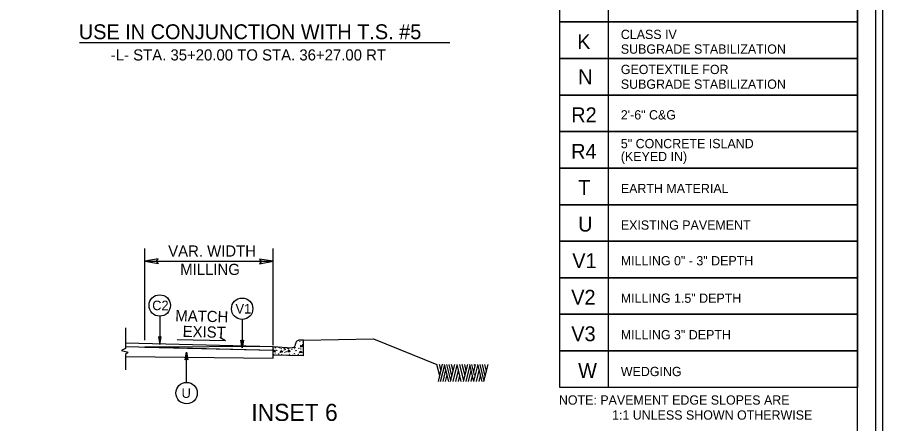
# Model space of a CAD drawing. Extents: x 573748 to 574632, y -54663 to -53209.
# Drawn here: x 574164.6 to 574281, y -53807.2 to -53752.5 of the extents above; entities that cross this region are included whole.
import ezdxf

# ---------------------------------------------------------------- set-up
doc = ezdxf.new("R2010")
doc.units = 0
for name, color, linetype in [('Prop Dimension', 7, 'Continuous'), ('Prop Dimension Text', 7, 'Continuous'), ('Prop Pavement Schedule Description CELL', 7, 'Continuous'), ('Prop Terminator CELL', 7, 'Continuous'), ('Sheet Plot Border Inside CELL', 7, 'Continuous'), ('Sheet Plot Border Outside CELL', 7, 'Continuous'), ('Sheet Typical CELL', 7, 'Continuous'), ('Typical Arrow Superelevation CELL', 7, 'Continuous'), ('Typical ID Circle CELL', 7, 'Continuous'), ('Typical Pavement Slope CELL', 7, 'Continuous'), ('Typical Terminator CELL', 7, 'Continuous'), ('Typical Text General CELL', 7, 'Continuous'), ('Typical Text ID Circle CELL', 7, 'Continuous')]:
    doc.layers.add(name, color=color, linetype=linetype)

msp = doc.modelspace()

# ---------------------------------------------------------------- linework, layer by layer
at = {"layer": 'Prop Dimension'}
for p, q in [((574181.74, -53795.97), (574181.74, -53783.61)), ((574198.97, -53796.66), (574198.97, -53783.61)), ((574181.74, -53785.35), (574198.97, -53785.35)), ((574179.11, -53794.3), (574179.11, -53797.07)), ((574203.07, -53795.99), (574202.52, -53795.98)), ((574203.07, -53795.99), (574212.48, -53795.79)), ((574203.07, -53798.09), (574203.07, -53795.99)), ((574212.48, -53795.79), (574221.01, -53799.23)), ((574179.11, -53797.07), (574178.61, -53797.37)), ((574178.61, -53797.37), (574179.47, -53797.57)), ((574179.47, -53797.57), (574179.11, -53797.92)), ((574198.97, -53796.81), (574181.74, -53796.91)), ((574181.74, -53796.91), (574198.97, -53797.32)), ((574198.97, -53797.99), (574198.97, -53796.81)), ((574198.97, -53796.81), (574201.47, -53796.98)), ((574198.97, -53797.32), (574198.97, -53796.81)), ((574199, -53797.52), (574199.19, -53797.27)), ((574199.26, -53797.51), (574199, -53797.52)), ((574199.19, -53797.27), (574199.26, -53797.51)), ((574199.94, -53797.62), (574200.08, -53797.38)), ((574200.29, -53797.54), (574199.94, -53797.62)), ((574200.08, -53797.38), (574200.29, -53797.54)), ((574200.96, -53797.53), (574201.14, -53797.29)), ((574201.21, -53797.53), (574200.96, -53797.53)), ((574201.14, -53797.29), (574201.21, -53797.53)), ((574202.01, -53796.49), (574202.01, -53796.47)), ((574202.55, -53797.68), (574202.69, -53797.45)), ((574202.9, -53797.61), (574202.55, -53797.68)), ((574202.65, -53796.68), (574202.68, -53796.87)), ((574202.97, -53796.79), (574202.65, -53796.68)), ((574202.68, -53796.87), (574202.97, -53796.79)), ((574202.69, -53797.45), (574202.9, -53797.61)), ((574179.11, -53797.92), (574179.11, -53799.97)), ((574179.11, -53798.19), (574198.97, -53798.39)), ((574198.97, -53798.39), (574198.97, -53797.99)), ((574203.07, -53798.09), (574198.97, -53797.99)), ((574221.39, -53800.78), (574221.01, -53799.23)), ((574221.21, -53801.52), (574221.77, -53799.22)), ((574221.57, -53800.1), (574221.35, -53799.23)), ((574221.51, -53801.52), (574222.06, -53799.3)), ((574222.61, -53801.52), (574222.05, -53799.23)), ((574222.61, -53800.3), (574222.35, -53799.23)), ((574223.03, -53800.76), (574222.65, -53799.23)), ((574222.85, -53801.52), (574223.41, -53799.23)), ((574223.2, -53800.11), (574222.98, -53799.23)), ((574223.21, -53801.52), (574223.75, -53799.34)), ((574224.29, -53801.52), (574223.72, -53799.23)), ((574224.62, -53801.45), (574224.08, -53799.23)), ((574224.8, -53800.74), (574224.43, -53799.23)), ((574224.61, -53801.52), (574225.17, -53799.23)), ((574224.96, -53800.08), (574224.75, -53799.23)), ((574224.95, -53801.52), (574225.48, -53799.35)), ((574225.99, -53801.55), (574225.42, -53799.26)), ((574226.07, -53800.7), (574225.72, -53799.26)), ((574225.98, -53800.23), (574226.22, -53799.26)), ((574225.99, -53801.55), (574226.53, -53799.38)), ((574226.07, -53799.37), (574226.05, -53799.26)), ((574226.11, -53799.34), (574226.09, -53799.23)), ((574227.08, -53801.55), (574226.51, -53799.26)), ((574227.35, -53801.48), (574226.81, -53799.26)), ((574227.52, -53800.82), (574227.13, -53799.26)), ((574227.34, -53801.55), (574227.9, -53799.26)), ((574227.69, -53800.14), (574227.48, -53799.26)), ((574221.85, -53801.52), (574222.23, -53799.96)), ((574222.17, -53801.52), (574222.39, -53800.62)), ((574222.88, -53801.38), (574222.61, -53800.3)), ((574223.56, -53801.52), (574223.92, -53800.03)), ((574223.9, -53801.52), (574224.09, -53800.73)), ((574225.25, -53801.55), (574225.62, -53800.07)), ((574225.61, -53801.55), (574225.79, -53800.78)), ((574226.01, -53800.11), (574225.98, -53800.02)), ((574226.35, -53801.55), (574226.71, -53800.07)), ((574226.7, -53801.55), (574226.88, -53800.78))]:
    msp.add_line(p, q, dxfattribs=at)
for centre in [(574202.58, -53796.14), (574203.04, -53796.23), (574199.02, -53797.05), (574199.26, -53797.02), (574199.3, -53796.92), (574199.46, -53797.33), (574199.83, -53796.99), (574200.08, -53797.1), (574200.45, -53797.32), (574200.49, -53797.11), (574200.56, -53797.62), (574200.61, -53797.19), (574200.76, -53797.53), (574200.84, -53797), (574201.04, -53797.12), (574201.45, -53797.05), (574201.5, -53797.26), (574201.81, -53797.45), (574201.88, -53797.09), (574201.92, -53796.99), (574202.07, -53797.39), (574202.45, -53797.06), (574202.7, -53797.17), (574202.92, -53796.6), (574199.01, -53797.88), (574199.25, -53797.7), (574199.37, -53797.95), (574199.74, -53797.83), (574200.1, -53797.92), (574200.42, -53797.96), (574200.86, -53798.02), (574201.2, -53797.89), (574201.63, -53797.95), (574201.87, -53797.77), (574201.98, -53798.01), (574202.36, -53797.89), (574202.72, -53797.99)]:
    msp.add_circle(centre, 0.0168, dxfattribs=at)
for centre, start, end in [((574202.51, -53796.48), 88.5196, 178.5196), ((574201.51, -53796.48), 266.1351, 358.5196)]:
    msp.add_arc(centre, 0.502, start, end, dxfattribs=at)
at = {"layer": 'Prop Pavement Schedule Description CELL'}
for points in [[(574244.08, -53753.13), (574237.56, -53753.13), (574237.56, -53748.22), (574277.57, -53748.22), (574277.57, -53753.13), (574244.08, -53753.13), (574244.08, -53748.22)], [(574244.08, -53758.05), (574237.56, -53758.05), (574237.56, -53753.13), (574277.57, -53753.13), (574277.57, -53758.05), (574244.08, -53758.05), (574244.08, -53753.13)], [(574244.08, -53762.97), (574237.56, -53762.97), (574237.56, -53758.05), (574277.57, -53758.05), (574277.57, -53762.97), (574244.08, -53762.97), (574244.08, -53758.05)], [(574244.08, -53767.89), (574237.56, -53767.89), (574237.56, -53762.97), (574277.57, -53762.97), (574277.57, -53767.89), (574244.08, -53767.89), (574244.08, -53762.97)], [(574244.08, -53772.81), (574237.56, -53772.81), (574237.56, -53767.89), (574277.57, -53767.89), (574277.57, -53772.81), (574244.08, -53772.81), (574244.08, -53767.89)], [(574244.08, -53777.73), (574237.56, -53777.73), (574237.56, -53772.81), (574277.57, -53772.81), (574277.57, -53777.73), (574244.08, -53777.73), (574244.08, -53772.81)], [(574244.08, -53782.64), (574237.56, -53782.64), (574237.56, -53777.73), (574277.57, -53777.73), (574277.57, -53782.64), (574244.08, -53782.64), (574244.08, -53777.73)], [(574244.08, -53787.56), (574237.56, -53787.56), (574237.56, -53782.64), (574277.57, -53782.64), (574277.57, -53787.56), (574244.08, -53787.56), (574244.08, -53782.64)], [(574244.08, -53792.48), (574237.56, -53792.48), (574237.56, -53787.56), (574277.57, -53787.56), (574277.57, -53792.48), (574244.08, -53792.48), (574244.08, -53787.56)], [(574244.08, -53797.4), (574237.56, -53797.4), (574237.56, -53792.48), (574277.57, -53792.48), (574277.57, -53797.4), (574244.08, -53797.4), (574244.08, -53792.48)], [(574244.08, -53802.32), (574237.56, -53802.32), (574237.56, -53797.4), (574277.57, -53797.4), (574277.57, -53802.32), (574244.08, -53802.32), (574244.08, -53797.4)]]:
    msp.add_lwpolyline(points, dxfattribs=at)
at = {"layer": 'Prop Terminator CELL'}
for points in [[(574183.53, -53785.02), (574181.74, -53785.35), (574183.55, -53785.65), (574183.32, -53785.33)], [(574197.17, -53785.69), (574198.97, -53785.35), (574197.16, -53785.06), (574197.39, -53785.37)]]:
    msp.add_lwpolyline(points, close=True, dxfattribs=at)
at = {"layer": 'Sheet Plot Border Inside CELL'}
msp.add_lwpolyline([(574280.07, -53683.17), (573946.77, -53683.17), (573946.77, -53894.19), (574280.07, -53894.19)], close=True, dxfattribs=at)
at = {"layer": 'Sheet Plot Border Outside CELL'}
msp.add_lwpolyline([(574280.97, -53678.68), (573944.17, -53678.68), (573944.17, -53898.68), (574280.97, -53898.68)], close=True, dxfattribs=at)
at = {"layer": 'Sheet Typical CELL'}
msp.add_lwpolyline([(574277.57, -53683.68), (573977.57, -53683.68), (573977.57, -53893.68), (574277.57, -53893.68)], close=True, dxfattribs=at)
at = {"layer": 'Typical Arrow Superelevation CELL'}
for q in [(574186.08, -53795.92), (574191.82, -53795.6)]:
    msp.add_line((574192.6, -53796.08), q, dxfattribs=at)
at = {"layer": 'Typical ID Circle CELL'}
for p, q in [((574183.74, -53792.74), (574183.74, -53796.57)), ((574194.82, -53793.18), (574194.82, -53797.01)), ((574187.34, -53801.65), (574187.34, -53797.57))]:
    msp.add_line(p, q, dxfattribs=at)
for centre in [(574183.74, -53791.3), (574194.82, -53791.74), (574187.34, -53803.1)]:
    msp.add_circle(centre, 1.44, dxfattribs=at)
at = {"layer": 'Typical Pavement Slope CELL'}
for p, q in [((574179.11, -53796.33), (574198.97, -53796.81)), ((574179.11, -53796.84), (574198.97, -53797.32))]:
    msp.add_line(p, q, dxfattribs=at)
at = {"layer": 'Typical Terminator CELL'}
for points in [[(574183.56, -53795.51), (574183.74, -53796.57), (574183.93, -53795.51), (574183.74, -53795.64)], [(574195.01, -53795.95), (574194.82, -53797.01), (574194.64, -53795.95), (574194.82, -53796.08)], [(574187.15, -53798.62), (574187.34, -53797.57), (574187.52, -53798.63), (574187.34, -53798.49)]]:
    msp.add_lwpolyline(points, close=True, dxfattribs=at)
at = {"layer": 'Typical Text General CELL'}
msp.add_line((574222.75, -53755.95), (574172.94, -53755.95), dxfattribs=at)

# ---------------------------------------------------------------- texts
at = {"layer": 'Prop Dimension Text'}
for s, height, p in [('VAR. WIDTH', 1.5, (574184.87, -53784.72)), ('MILLING', 1.5, (574186.49, -53787.19)), ('INSET 6', 2.3, (574196.05, -53806.84))]:
    msp.add_text(s, height=height, dxfattribs=at).set_placement(p)
for s, p in [('MATCH', (574185.81, -53793.41)), ('EXIST', (574186.8, -53795.53))]:
    msp.add_text(s, height=1.5, rotation=358.6506, dxfattribs=at).set_placement(p)
at = {"layer": 'Prop Pavement Schedule Description CELL'}
for s, height, p in [('CLASS IV', 1.25, (574245.75, -53755.43)), ('K', 2, (574239.89, -53756.79)), ('SUBGRADE STABILIZATION', 1.25, (574245.75, -53757.41)), ('GEOTEXTILE FOR', 1.25, (574245.75, -53760.15)), ('N', 2, (574240.01, -53761.51)), ('SUBGRADE STABILIZATION', 1.25, (574245.75, -53762.13)), ('R2', 2, (574239.08, -53766.63)), ('2\'-6" C&G', 1.25, (574245.75, -53766.26)), ('R4', 2, (574239.07, -53771.55)), ('5" CONCRETE ISLAND', 1.25, (574245.75, -53770.13)), ('(KEYED IN)', 1.25, (574245.75, -53771.87)), ('T', 2, (574240.01, -53776.43)), ('EARTH MATERIAL', 1.25, (574245.75, -53776.18)), ('U', 2, (574240.01, -53781.35)), ('EXISTING PAVEMENT', 1.25, (574245.75, -53781.1)), ('V1', 2, (574239.22, -53786.27)), ('MILLING 0" - 3" DEPTH', 1.25, (574245.75, -53785.9)), ('V2', 2, (574239.08, -53791.19)), ('MILLING 1.5" DEPTH', 1.25, (574245.75, -53790.94)), ('V3', 2, (574239.09, -53796.11)), ('MILLING 3" DEPTH', 1.25, (574245.75, -53795.86)), ('W', 2, (574240.01, -53801.06)), ('WEDGING', 1.25, (574245.75, -53800.81)), ('NOTE: PAVEMENT EDGE SLOPES ARE', 1.25, (574237.42, -53804.65)), ('1:1 UNLESS SHOWN OTHERWISE', 1.25, (574244.57, -53806.67))]:
    msp.add_text(s, height=height, dxfattribs=at).set_placement(p)
at = {"layer": 'Typical Text General CELL'}
for s, height, p in [('USE IN CONJUNCTION WITH T.S. #5', 2, (574172.85, -53755.45)), ('-L- STA. 35+20.00 TO STA. 36+27.00 RT', 1.5, (574177.15, -53758.32))]:
    msp.add_text(s, height=height, dxfattribs=at).set_placement(p)
at = {"layer": 'Typical Text ID Circle CELL'}
for s, height, p in [('C2', 1.291, (574182.72, -53791.94)), ('V1', 1.291, (574193.93, -53792.38)), ('U', 1.29, (574186.67, -53803.74))]:
    msp.add_text(s, height=height, dxfattribs=at).set_placement(p)

doc.saveas('drawing.dxf')
